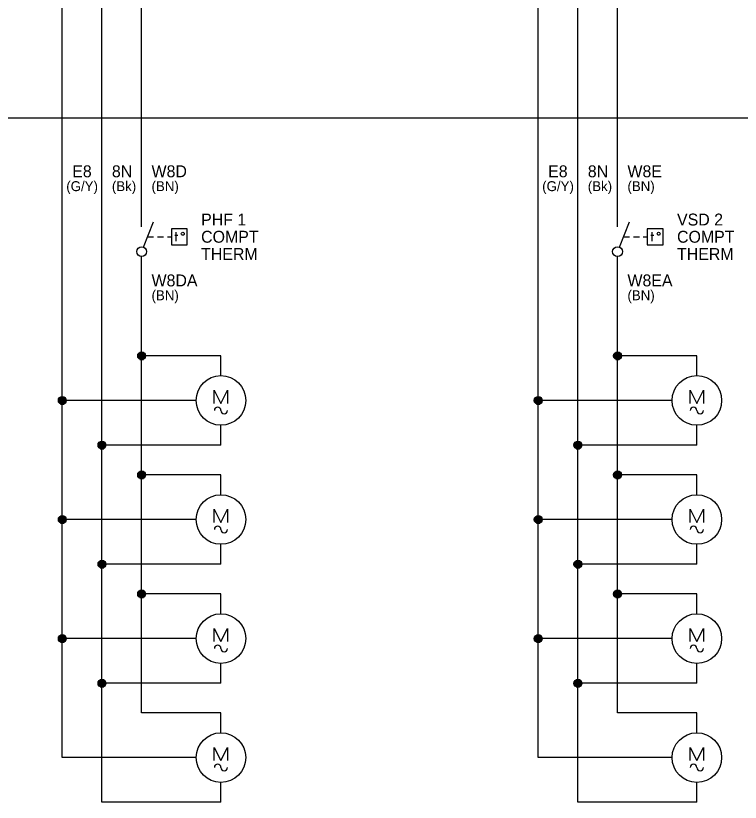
# Model space of a CAD drawing. Extents: x 0 to 841, y 0 to 594.
# Drawn here: x 408.3 to 590.9, y 107.5 to 305.7 of the extents above; entities that cross this region are included whole.
import ezdxf

# ---------------------------------------------------------------- set-up
doc = ezdxf.new("R2010")
doc.units = 0
doc.layers.add('Level 1', color=7, linetype='Continuous')
doc.layers.add('Level 10', color=7, linetype='Continuous')

msp = doc.modelspace()

# ---------------------------------------------------------------- linework, layer by layer
at = {"layer": 'Level 1'}
for p, q in [((440, 255), (440, 528.75)), ((560, 255), (560, 528.75)), ((430, 107.5), (430, 518.75)), ((550, 107.5), (550, 518.75)), ((420, 118.75), (420, 508.75)), ((540, 118.75), (540, 508.75)), ((28, 280), (829, 280)), ((440, 252.5), (440, 255)), ((440.46, 247.41), (443, 253.75)), ((560, 252.5), (560, 255)), ((560.46, 247.41), (563, 253.75)), ((441.5, 250), (443, 250)), ((444, 250), (445.5, 250)), ((446.5, 250), (447.5, 250)), ((561.5, 250), (563, 250)), ((564, 250), (565.5, 250)), ((566.5, 250), (567.5, 250)), ((440, 130), (440, 245)), ((560, 130), (560, 245)), ((460, 220), (440, 220)), ((460, 215), (460, 220)), ((580, 220), (560, 220)), ((580, 215), (580, 220)), ((453.75, 208.75), (420, 208.75)), ((573.75, 208.75), (540, 208.75)), ((460, 197.5), (460, 202.5)), ((580, 197.5), (580, 202.5)), ((460, 197.5), (430, 197.5)), ((580, 197.5), (550, 197.5)), ((460, 190), (440, 190)), ((460, 185), (460, 190)), ((580, 190), (560, 190)), ((580, 185), (580, 190)), ((453.75, 178.75), (420, 178.75)), ((573.75, 178.75), (540, 178.75)), ((460, 167.5), (460, 172.5)), ((580, 167.5), (580, 172.5)), ((460, 167.5), (430, 167.5)), ((580, 167.5), (550, 167.5)), ((460, 160), (440, 160)), ((460, 155), (460, 160)), ((580, 160), (560, 160)), ((580, 155), (580, 160)), ((453.75, 148.75), (420, 148.75)), ((573.75, 148.75), (540, 148.75)), ((460, 137.5), (460, 142.5)), ((580, 137.5), (580, 142.5)), ((460, 137.5), (430, 137.5)), ((580, 137.5), (550, 137.5)), ((460, 130), (440, 130)), ((460, 125), (460, 130)), ((580, 130), (560, 130)), ((580, 125), (580, 130)), ((453.75, 118.75), (420, 118.75)), ((573.75, 118.75), (540, 118.75)), ((460, 107.5), (460, 112.5)), ((580, 107.5), (580, 112.5)), ((460, 107.5), (430, 107.5)), ((580, 107.5), (550, 107.5))]:
    msp.add_line(p, q, dxfattribs=at)
for points in [[(447.5, 248), (451.5, 248), (451.5, 252), (447.5, 252)], [(567.5, 248), (571.5, 248), (571.5, 252), (567.5, 252)]]:
    msp.add_lwpolyline(points, close=True, dxfattribs=at)
for points in [[(448.38, 250.38), (449.13, 250.38)], [(448.63, 251.13), (448.63, 248.87)], [(450.36, 250.38), (450.18, 250.42), (450.05, 250.56), (449.99, 250.76), (450.05, 250.94), (450.18, 251.07), (450.36, 251.13), (450.56, 251.07), (450.7, 250.94), (450.74, 250.76), (450.7, 250.56), (450.56, 250.42), (450.36, 250.38)], [(568.38, 250.38), (569.13, 250.38)], [(568.63, 251.13), (568.63, 248.87)], [(570.36, 250.38), (570.18, 250.42), (570.05, 250.56), (569.99, 250.76), (570.05, 250.94), (570.18, 251.07), (570.36, 251.13), (570.56, 251.07), (570.7, 250.94), (570.74, 250.76), (570.7, 250.56), (570.56, 250.42), (570.36, 250.38)]]:
    msp.add_lwpolyline(points, dxfattribs=at)
for centre in [(440, 246.25), (560, 246.25)]:
    msp.add_circle(centre, 1.25, dxfattribs=at)
at = {"layer": 'Level 10'}
for p, q in [((439.05, 220.3), (440.95, 220.3)), ((439.2, 220.6), (440.8, 220.6)), ((439.56, 220.9), (440.44, 220.9)), ((440, 221), (440, 221)), ((559.05, 220.3), (560.95, 220.3)), ((559.2, 220.6), (560.8, 220.6)), ((559.56, 220.9), (560.44, 220.9)), ((560, 221), (560, 221)), ((439, 220), (440.99, 220)), ((439.05, 219.7), (440.95, 219.7)), ((439.2, 219.4), (440.8, 219.4)), ((439.56, 219.1), (440.44, 219.1)), ((559, 220), (560.99, 220)), ((559.05, 219.7), (560.95, 219.7)), ((559.2, 219.4), (560.8, 219.4)), ((559.56, 219.1), (560.44, 219.1)), ((458.33, 211.33), (460, 208)), ((458.33, 208), (458.33, 211.33)), ((460, 208), (461.67, 211.33)), ((461.67, 211.33), (461.67, 208)), ((578.33, 211.33), (580, 208)), ((578.33, 208), (578.33, 211.33)), ((580, 208), (581.67, 211.33)), ((581.67, 211.33), (581.67, 208)), ((419, 208.75), (420.99, 208.75)), ((419.05, 209.05), (420.95, 209.05)), ((419.05, 208.45), (420.95, 208.45)), ((419.2, 209.35), (420.8, 209.35)), ((419.2, 208.15), (420.8, 208.15)), ((419.56, 209.65), (420.44, 209.65)), ((420, 209.75), (420, 209.75)), ((539, 208.75), (540.99, 208.75)), ((539.05, 209.05), (540.95, 209.05)), ((539.05, 208.45), (540.95, 208.45)), ((539.2, 209.35), (540.8, 209.35)), ((539.2, 208.15), (540.8, 208.15)), ((539.56, 209.65), (540.44, 209.65)), ((540, 209.75), (540, 209.75)), ((419.56, 207.85), (420.44, 207.85)), ((539.56, 207.85), (540.44, 207.85)), ((429.56, 198.4), (430.44, 198.4)), ((430, 198.5), (430, 198.5)), ((549.56, 198.4), (550.44, 198.4)), ((550, 198.5), (550, 198.5)), ((429, 197.5), (430.99, 197.5)), ((429.05, 197.8), (430.95, 197.8)), ((429.05, 197.2), (430.95, 197.2)), ((429.2, 198.1), (430.8, 198.1)), ((429.2, 196.9), (430.8, 196.9)), ((429.56, 196.6), (430.44, 196.6)), ((549, 197.5), (550.99, 197.5)), ((549.05, 197.8), (550.95, 197.8)), ((549.05, 197.2), (550.95, 197.2)), ((549.2, 198.1), (550.8, 198.1)), ((549.2, 196.9), (550.8, 196.9)), ((549.56, 196.6), (550.44, 196.6)), ((439.05, 190.3), (440.95, 190.3)), ((439.2, 190.6), (440.8, 190.6)), ((439.56, 190.9), (440.44, 190.9)), ((440, 191), (440, 191)), ((559.05, 190.3), (560.95, 190.3)), ((559.2, 190.6), (560.8, 190.6)), ((559.56, 190.9), (560.44, 190.9)), ((560, 191), (560, 191)), ((439, 190), (440.99, 190)), ((439.05, 189.7), (440.95, 189.7)), ((439.2, 189.4), (440.8, 189.4)), ((439.56, 189.1), (440.44, 189.1)), ((559, 190), (560.99, 190)), ((559.05, 189.7), (560.95, 189.7)), ((559.2, 189.4), (560.8, 189.4)), ((559.56, 189.1), (560.44, 189.1)), ((458.33, 181.33), (460, 178)), ((458.33, 178), (458.33, 181.33)), ((460, 178), (461.67, 181.33)), ((461.67, 181.33), (461.67, 178)), ((578.33, 181.33), (580, 178)), ((578.33, 178), (578.33, 181.33)), ((580, 178), (581.67, 181.33)), ((581.67, 181.33), (581.67, 178)), ((419, 178.75), (420.99, 178.75)), ((419.05, 179.05), (420.95, 179.05)), ((419.05, 178.45), (420.95, 178.45)), ((419.2, 179.35), (420.8, 179.35)), ((419.56, 179.65), (420.44, 179.65)), ((420, 179.75), (420, 179.75)), ((539, 178.75), (540.99, 178.75)), ((539.05, 179.05), (540.95, 179.05)), ((539.05, 178.45), (540.95, 178.45)), ((539.2, 179.35), (540.8, 179.35)), ((539.56, 179.65), (540.44, 179.65)), ((540, 179.75), (540, 179.75)), ((419.2, 178.15), (420.8, 178.15)), ((419.56, 177.85), (420.44, 177.85)), ((539.2, 178.15), (540.8, 178.15)), ((539.56, 177.85), (540.44, 177.85)), ((430, 168.5), (430, 168.5)), ((550, 168.5), (550, 168.5)), ((429, 167.5), (430.99, 167.5)), ((429.05, 167.8), (430.95, 167.8)), ((429.05, 167.2), (430.95, 167.2)), ((429.2, 168.1), (430.8, 168.1)), ((429.2, 166.9), (430.8, 166.9)), ((429.56, 168.4), (430.44, 168.4)), ((429.56, 166.6), (430.44, 166.6)), ((549, 167.5), (550.99, 167.5)), ((549.05, 167.8), (550.95, 167.8)), ((549.05, 167.2), (550.95, 167.2)), ((549.2, 168.1), (550.8, 168.1)), ((549.2, 166.9), (550.8, 166.9)), ((549.56, 168.4), (550.44, 168.4)), ((549.56, 166.6), (550.44, 166.6)), ((439.2, 160.6), (440.8, 160.6)), ((439.56, 160.9), (440.44, 160.9)), ((440, 161), (440, 161)), ((559.2, 160.6), (560.8, 160.6)), ((559.56, 160.9), (560.44, 160.9)), ((560, 161), (560, 161)), ((439, 160), (440.99, 160)), ((439.05, 160.3), (440.95, 160.3)), ((439.05, 159.7), (440.95, 159.7)), ((439.2, 159.4), (440.8, 159.4)), ((439.56, 159.1), (440.44, 159.1)), ((559, 160), (560.99, 160)), ((559.05, 160.3), (560.95, 160.3)), ((559.05, 159.7), (560.95, 159.7)), ((559.2, 159.4), (560.8, 159.4)), ((559.56, 159.1), (560.44, 159.1)), ((458.33, 151.33), (460, 148)), ((458.33, 148), (458.33, 151.33)), ((460, 148), (461.67, 151.33)), ((461.67, 151.33), (461.67, 148)), ((578.33, 151.33), (580, 148)), ((578.33, 148), (578.33, 151.33)), ((580, 148), (581.67, 151.33)), ((581.67, 151.33), (581.67, 148)), ((419, 148.75), (420.99, 148.75)), ((419.05, 149.05), (420.95, 149.05)), ((419.2, 149.35), (420.8, 149.35)), ((419.56, 149.65), (420.44, 149.65)), ((420, 149.75), (420, 149.75)), ((539, 148.75), (540.99, 148.75)), ((539.05, 149.05), (540.95, 149.05)), ((539.2, 149.35), (540.8, 149.35)), ((539.56, 149.65), (540.44, 149.65)), ((540, 149.75), (540, 149.75)), ((419.05, 148.45), (420.95, 148.45)), ((419.2, 148.15), (420.8, 148.15)), ((419.56, 147.85), (420.44, 147.85)), ((539.05, 148.45), (540.95, 148.45)), ((539.2, 148.15), (540.8, 148.15)), ((539.56, 147.85), (540.44, 147.85)), ((429, 137.5), (430.99, 137.5)), ((429.05, 137.8), (430.95, 137.8)), ((429.05, 137.2), (430.95, 137.2)), ((429.2, 138.1), (430.8, 138.1)), ((429.2, 136.9), (430.8, 136.9)), ((429.56, 138.4), (430.44, 138.4)), ((430, 138.5), (430, 138.5)), ((549, 137.5), (550.99, 137.5)), ((549.05, 137.8), (550.95, 137.8)), ((549.05, 137.2), (550.95, 137.2)), ((549.2, 138.1), (550.8, 138.1)), ((549.2, 136.9), (550.8, 136.9)), ((549.56, 138.4), (550.44, 138.4)), ((550, 138.5), (550, 138.5)), ((429.56, 136.6), (430.44, 136.6)), ((549.56, 136.6), (550.44, 136.6)), ((458.33, 121.33), (460, 118)), ((458.33, 118), (458.33, 121.33)), ((460, 118), (461.67, 121.33)), ((461.67, 121.33), (461.67, 118)), ((578.33, 121.33), (580, 118)), ((578.33, 118), (578.33, 121.33)), ((580, 118), (581.67, 121.33)), ((581.67, 121.33), (581.67, 118))]:
    msp.add_line(p, q, dxfattribs=at)
for centre, radius in [((440, 220), 1), ((560, 220), 1), ((460, 208.75), 6.25), ((580, 208.75), 6.25), ((420, 208.75), 1), ((540, 208.75), 1), ((430, 197.5), 1), ((550, 197.5), 1), ((440, 190), 1), ((560, 190), 1), ((460, 178.75), 6.25), ((580, 178.75), 6.25), ((420, 178.75), 1), ((540, 178.75), 1), ((430, 167.5), 1), ((550, 167.5), 1), ((440, 160), 1), ((560, 160), 1), ((460, 148.75), 6.25), ((580, 148.75), 6.25), ((420, 148.75), 1), ((540, 148.75), 1), ((430, 137.5), 1), ((550, 137.5), 1), ((460, 118.75), 6.25), ((580, 118.75), 6.25)]:
    msp.add_circle(centre, radius, dxfattribs=at)
for centre, start, end in [((459.17, 206.25), 0, 180), ((460.83, 206.25), 180, 0), ((579.17, 206.25), 0, 180), ((580.83, 206.25), 180, 0), ((459.17, 176.25), 0, 180), ((579.17, 176.25), 0, 180), ((460.83, 176.25), 180, 0), ((580.83, 176.25), 180, 0), ((459.17, 146.25), 0, 180), ((579.17, 146.25), 0, 180), ((460.83, 146.25), 180, 0), ((580.83, 146.25), 180, 0), ((459.17, 116.25), 0, 180), ((579.17, 116.25), 0, 180), ((460.83, 116.25), 180, 0), ((580.83, 116.25), 180, 0)]:
    msp.add_arc(centre, 0.83, start, end, dxfattribs=at)

# ---------------------------------------------------------------- texts
at = {"layer": 'Level 1'}
for s, height, p in [('E8', 3, (422.5, 265)), ('8N', 3, (432.5, 265)), ('W8D', 3, (442.5, 265)), ('E8', 3, (542.5, 265)), ('8N', 3, (552.5, 265)), ('W8E', 3, (562.5, 265)), ('(G/Y)', 2.50002, (421, 261.49998)), ('(Bk)', 2.50002, (432.5, 261.49998)), ('(BN)', 2.50002, (442.5, 261.49998)), ('(G/Y)', 2.50002, (541, 261.49998)), ('(Bk)', 2.50002, (552.5, 261.49998)), ('(BN)', 2.50002, (562.5, 261.49998)), ('PHF 1', 3, (455, 252.8418)), ('VSD 2', 3, (575, 252.8418)), ('COMPT', 3, (455, 248.5)), ('COMPT', 3, (575, 248.5)), ('THERM', 3, (455, 244.1582)), ('THERM', 3, (575, 244.1582)), ('W8DA', 3, (442.5, 237.5)), ('W8EA', 3, (562.5, 237.5)), ('(BN)', 2.50002, (442.5, 233.99998)), ('(BN)', 2.50002, (562.5, 233.99998))]:
    msp.add_text(s, height=height, dxfattribs=at).set_placement(p)

doc.saveas('drawing.dxf')
